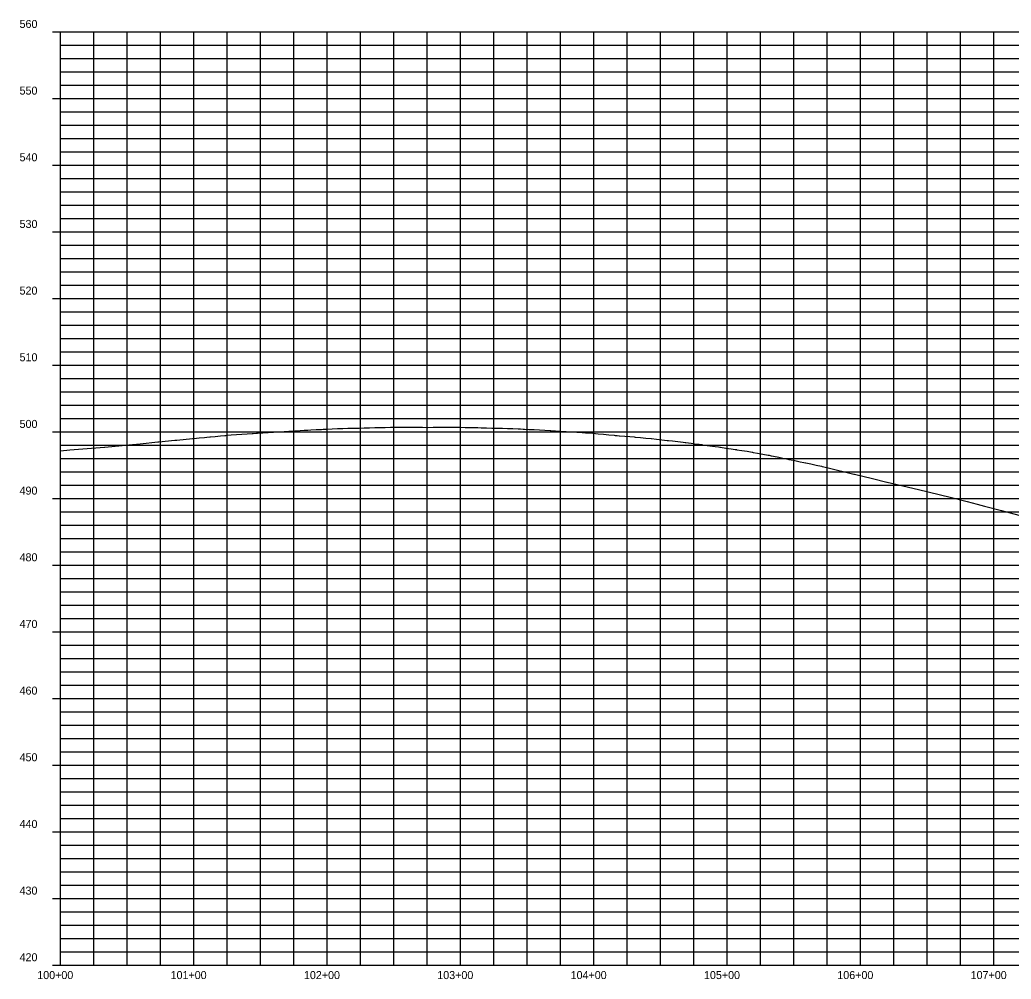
# Model space of a CAD drawing. Extents: x 1054002 to 1056762, y 395173 to 397393.
# Drawn here: x 1054002 to 1054745, y 396673 to 397393 of the extents above; entities that cross this region are included whole.
import ezdxf

# ---------------------------------------------------------------- set-up
doc = ezdxf.new("R2010")
doc.units = 0
for name, color, linetype in [('63', 7, 'Continuous'), ('R_Axis_Annotation', 7, 'Continuous'), ('R_Exist Surface', 7, 'Continuous'), ('R_Grid', 7, 'Continuous'), ('R_Grid Annot', 7, 'Continuous'), ('R_Grid_Minor', 7, 'Continuous')]:
    doc.layers.add(name, color=color, linetype=linetype)

msp = doc.modelspace()

# ---------------------------------------------------------------- linework, layer by layer
at = {"layer": 'R_Exist Surface'}
msp.add_lwpolyline([(1054032.29, 397069.3), (1054039.34, 397069.89), (1054039.43, 397069.9), (1054052.41, 397070.98), (1054052.42, 397070.98), (1054065.39, 397072.06), (1054065.47, 397072.06), (1054078.44, 397073.14), (1054083.55, 397073.66), (1054092.06, 397074.53), (1054105.29, 397075.88), (1054105.96, 397075.96), (1054118.16, 397077.16), (1054119.57, 397077.31), (1054131.32, 397078.47), (1054132.29, 397078.57), (1054136.28, 397078.96), (1054140.27, 397079.34), (1054142.1, 397079.51), (1054144.26, 397079.74), (1054144.8, 397079.8), (1054148.25, 397080.11), (1054152.24, 397080.47), (1054155.52, 397080.76), (1054156.23, 397080.83), (1054157.51, 397080.95), (1054160.22, 397081.15), (1054164.21, 397081.45), (1054168.19, 397081.73), (1054172.18, 397082.01), (1054176.17, 397082.27), (1054176.75, 397082.31), (1054179.26, 397082.51), (1054180.16, 397082.58), (1054181.65, 397082.7), (1054184.15, 397082.85), (1054188.14, 397083.09), (1054192.13, 397083.31), (1054196.12, 397083.53), (1054200.11, 397083.73), (1054202.29, 397083.83), (1054203.65, 397083.92), (1054204.1, 397083.95), (1054208.09, 397084.21), (1054212.08, 397084.45), (1054214.94, 397084.62), (1054216.06, 397084.7), (1054217.75, 397084.82), (1054220.05, 397084.95), (1054224.04, 397085.16), (1054228.03, 397085.35), (1054229.28, 397085.41), (1054231.43, 397085.54), (1054232.02, 397085.56), (1054236.01, 397085.72), (1054240, 397085.87), (1054242.91, 397085.97), (1054243.99, 397086.01), (1054247.91, 397086.12), (1054247.98, 397086.12), (1054251.97, 397086.22), (1054255.49, 397086.29), (1054255.96, 397086.31), (1054256.25, 397086.32), (1054259.95, 397086.44), (1054263.93, 397086.56), (1054267.92, 397086.66), (1054268.32, 397086.67), (1054268.68, 397086.68), (1054271.91, 397086.75), (1054275.9, 397086.82), (1054279.89, 397086.87), (1054281.12, 397086.88), (1054281.54, 397086.89), (1054283.88, 397086.91), (1054287.87, 397086.93), (1054291.86, 397086.94), (1054293.91, 397086.94), (1054294.92, 397086.94), (1054295.85, 397086.94), (1054299.84, 397086.92), (1054303.83, 397086.88), (1054306.73, 397086.84), (1054307.81, 397086.86), (1054311.8, 397086.9), (1054315.79, 397086.92), (1054318.11, 397086.92), (1054319.78, 397086.94), (1054320.3, 397086.94), (1054323.77, 397086.93), (1054327.76, 397086.91), (1054331.75, 397086.87), (1054331.82, 397086.87), (1054335.74, 397086.81), (1054339.73, 397086.75), (1054343.52, 397086.67), (1054343.72, 397086.66), (1054345.39, 397086.64), (1054347.71, 397086.58), (1054351.7, 397086.47), (1054355.68, 397086.35), (1054356.97, 397086.3), (1054359.67, 397086.24), (1054363.66, 397086.14), (1054367.65, 397086.02), (1054371.64, 397085.89), (1054375.63, 397085.75), (1054377.2, 397085.69), (1054379.22, 397085.55), (1054379.62, 397085.54), (1054380.23, 397085.51), (1054383.61, 397085.36), (1054387.6, 397085.17), (1054391.59, 397084.97), (1054395.58, 397084.74), (1054399.57, 397084.5), (1054400.14, 397084.47), (1054401.93, 397084.35), (1054403.55, 397084.27), (1054407.54, 397084.05), (1054411.53, 397083.81), (1054415.52, 397083.56), (1054419.51, 397083.29), (1054423.5, 397083.01), (1054424.44, 397082.94), (1054425.24, 397082.87), (1054426.11, 397082.79), (1054427.49, 397082.68), (1054431.48, 397082.37), (1054435.47, 397082.03), (1054439.46, 397081.68), (1054443.45, 397081.31), (1054447.44, 397080.92), (1054448.33, 397080.83), (1054449.82, 397080.71), (1054451.18, 397080.6), (1054451.42, 397080.58), (1054455.41, 397080.26), (1054459.4, 397079.92), (1054462.6, 397079.63), (1054463.17, 397079.58), (1054463.39, 397079.56), (1054467.38, 397079.19), (1054471.37, 397078.8), (1054475.35, 397078.39), (1054475.36, 397078.39), (1054475.49, 397078.38), (1054479.35, 397077.97), (1054483.34, 397077.53), (1054487.33, 397077.08), (1054488.05, 397076.99), (1054488.21, 397076.98), (1054491.32, 397076.62), (1054495.3, 397076.13), (1054499.29, 397075.63), (1054500.72, 397075.45), (1054501.29, 397075.39), (1054503.28, 397075.15), (1054507.27, 397074.66), (1054507.61, 397074.61), (1054511.26, 397074.15), (1054513.27, 397073.88), (1054513.72, 397073.82), (1054515.25, 397073.61), (1054519.24, 397073.07), (1054523.23, 397072.51), (1054525.78, 397072.15), (1054526.86, 397071.98), (1054527.22, 397071.93), (1054531.21, 397071.35), (1054535.2, 397070.76), (1054538.34, 397070.28), (1054539.19, 397070.14), (1054539.57, 397070.08), (1054543.17, 397069.52), (1054547.16, 397068.89), (1054550.98, 397068.27), (1054551.15, 397068.24), (1054551.89, 397068.11), (1054555.14, 397067.51), (1054559.13, 397066.76), (1054563.12, 397066), (1054563.76, 397065.87), (1054565.38, 397065.52), (1054567.11, 397065.18), (1054571.1, 397064.39), (1054575.09, 397063.59), (1054576.69, 397063.27), (1054578.51, 397062.85), (1054579.08, 397062.74), (1054583.07, 397061.92), (1054587.06, 397061.1), (1054589.75, 397060.54), (1054591.04, 397060.23), (1054591.24, 397060.19), (1054595.03, 397059.39), (1054599.02, 397058.55), (1054602.93, 397057.73), (1054603.01, 397057.71), (1054603.56, 397057.57), (1054607, 397056.74), (1054627.31, 397051.81), (1054627.67, 397051.71), (1054641.33, 397048.4), (1054651.9, 397045.84), (1054652.22, 397045.76), (1054675.65, 397040.19), (1054675.84, 397040.14), (1054699.4, 397034.54), (1054699.43, 397034.54), (1054712.29, 397031.18), (1054712.3, 397031.18), (1054719.75, 397029.24), (1054725.17, 397027.82), (1054738.01, 397024.47), (1054738.07, 397024.45), (1054750.91, 397021.1)], dxfattribs=at)
at = {"layer": 'R_Grid'}
for p, q in [((1054032.29, 396683.41), (1054032.29, 397383.41)), ((1054032.29, 397383.41), (1056732.29, 397383.41)), ((1054032.29, 397383.41), (1056732.29, 397383.41)), ((1054132.29, 396683.41), (1054132.29, 397383.41)), ((1054232.29, 396683.41), (1054232.29, 397383.41)), ((1054332.29, 396683.41), (1054332.29, 397383.41)), ((1054432.29, 396683.41), (1054432.29, 397383.41)), ((1054532.29, 396683.41), (1054532.29, 397383.41)), ((1054632.29, 396683.41), (1054632.29, 397383.41)), ((1054732.29, 396683.41), (1054732.29, 397383.41)), ((1054032.29, 397333.41), (1056732.29, 397333.41)), ((1054032.29, 397283.41), (1056732.29, 397283.41)), ((1054032.29, 397233.41), (1056732.29, 397233.41)), ((1054032.29, 397183.41), (1056732.29, 397183.41)), ((1054032.29, 397133.41), (1056732.29, 397133.41)), ((1054032.29, 397083.41), (1056732.29, 397083.41)), ((1054032.29, 397033.41), (1056732.29, 397033.41)), ((1054032.29, 396983.41), (1056732.29, 396983.41)), ((1054032.29, 396933.41), (1056732.29, 396933.41)), ((1054032.29, 396883.41), (1056732.29, 396883.41)), ((1054032.29, 396833.41), (1056732.29, 396833.41)), ((1054032.29, 396783.41), (1056732.29, 396783.41)), ((1054032.29, 396733.41), (1056732.29, 396733.41)), ((1054032.29, 396683.41), (1056732.29, 396683.41))]:
    msp.add_line(p, q, dxfattribs=at)
at = {"layer": 'R_Grid Annot'}
for p, q in [((1054026.29, 397383.41), (1054032.29, 397383.41)), ((1054026.29, 397383.41), (1054032.29, 397383.41)), ((1054032.29, 397373.41), (1054035.29, 397373.41)), ((1054032.29, 397363.41), (1054035.29, 397363.41)), ((1054032.29, 397353.41), (1054035.29, 397353.41)), ((1054032.29, 397343.41), (1054035.29, 397343.41)), ((1054026.29, 397333.41), (1054032.29, 397333.41)), ((1054032.29, 397323.41), (1054035.29, 397323.41)), ((1054032.29, 397313.41), (1054035.29, 397313.41)), ((1054032.29, 397303.41), (1054035.29, 397303.41)), ((1054032.29, 397293.41), (1054035.29, 397293.41)), ((1054026.29, 397283.41), (1054032.29, 397283.41)), ((1054032.29, 397273.41), (1054035.29, 397273.41)), ((1054032.29, 397263.41), (1054035.29, 397263.41)), ((1054032.29, 397253.41), (1054035.29, 397253.41)), ((1054032.29, 397243.41), (1054035.29, 397243.41)), ((1054026.29, 397233.41), (1054032.29, 397233.41)), ((1054032.29, 397223.41), (1054035.29, 397223.41)), ((1054032.29, 397213.41), (1054035.29, 397213.41)), ((1054032.29, 397203.41), (1054035.29, 397203.41)), ((1054032.29, 397193.41), (1054035.29, 397193.41)), ((1054026.29, 397183.41), (1054032.29, 397183.41)), ((1054032.29, 397173.41), (1054035.29, 397173.41)), ((1054032.29, 397163.41), (1054035.29, 397163.41)), ((1054032.29, 397153.41), (1054035.29, 397153.41)), ((1054032.29, 397143.41), (1054035.29, 397143.41)), ((1054026.29, 397133.41), (1054032.29, 397133.41)), ((1054032.29, 397123.41), (1054035.29, 397123.41)), ((1054032.29, 397113.41), (1054035.29, 397113.41)), ((1054032.29, 397103.41), (1054035.29, 397103.41)), ((1054032.29, 397093.41), (1054035.29, 397093.41)), ((1054026.29, 397083.41), (1054032.29, 397083.41)), ((1054032.29, 397073.41), (1054035.29, 397073.41)), ((1054032.29, 397063.41), (1054035.29, 397063.41)), ((1054032.29, 397053.41), (1054035.29, 397053.41)), ((1054032.29, 397043.41), (1054035.29, 397043.41)), ((1054026.29, 397033.41), (1054032.29, 397033.41)), ((1054032.29, 397023.41), (1054035.29, 397023.41)), ((1054032.29, 397013.41), (1054035.29, 397013.41)), ((1054032.29, 397003.41), (1054035.29, 397003.41)), ((1054032.29, 396993.41), (1054035.29, 396993.41)), ((1054026.29, 396983.41), (1054032.29, 396983.41)), ((1054032.29, 396973.41), (1054035.29, 396973.41)), ((1054032.29, 396963.41), (1054035.29, 396963.41)), ((1054032.29, 396953.41), (1054035.29, 396953.41)), ((1054032.29, 396943.41), (1054035.29, 396943.41)), ((1054026.29, 396933.41), (1054032.29, 396933.41)), ((1054032.29, 396923.41), (1054035.29, 396923.41)), ((1054032.29, 396913.41), (1054035.29, 396913.41)), ((1054032.29, 396903.41), (1054035.29, 396903.41)), ((1054032.29, 396893.41), (1054035.29, 396893.41)), ((1054026.29, 396883.41), (1054032.29, 396883.41)), ((1054032.29, 396873.41), (1054035.29, 396873.41)), ((1054032.29, 396863.41), (1054035.29, 396863.41)), ((1054032.29, 396853.41), (1054035.29, 396853.41)), ((1054032.29, 396843.41), (1054035.29, 396843.41)), ((1054026.29, 396833.41), (1054032.29, 396833.41)), ((1054032.29, 396823.41), (1054035.29, 396823.41)), ((1054032.29, 396813.41), (1054035.29, 396813.41)), ((1054032.29, 396803.41), (1054035.29, 396803.41)), ((1054032.29, 396793.41), (1054035.29, 396793.41)), ((1054026.29, 396783.41), (1054032.29, 396783.41)), ((1054032.29, 396773.41), (1054035.29, 396773.41)), ((1054032.29, 396763.41), (1054035.29, 396763.41)), ((1054032.29, 396753.41), (1054035.29, 396753.41)), ((1054032.29, 396743.41), (1054035.29, 396743.41)), ((1054026.29, 396733.41), (1054032.29, 396733.41)), ((1054032.29, 396723.41), (1054035.29, 396723.41)), ((1054032.29, 396713.41), (1054035.29, 396713.41)), ((1054032.29, 396703.41), (1054035.29, 396703.41)), ((1054032.29, 396693.41), (1054035.29, 396693.41)), ((1054026.29, 396683.41), (1054032.29, 396683.41))]:
    msp.add_line(p, q, dxfattribs=at)
at = {"layer": 'R_Grid_Minor'}
for p, q in [((1054057.29, 396683.41), (1054057.29, 397383.41)), ((1054082.29, 396683.41), (1054082.29, 397383.41)), ((1054107.29, 396683.41), (1054107.29, 397383.41)), ((1054157.29, 396683.41), (1054157.29, 397383.41)), ((1054182.29, 396683.41), (1054182.29, 397383.41)), ((1054207.29, 396683.41), (1054207.29, 397383.41)), ((1054257.29, 396683.41), (1054257.29, 397383.41)), ((1054282.29, 396683.41), (1054282.29, 397383.41)), ((1054307.29, 396683.41), (1054307.29, 397383.41)), ((1054357.29, 396683.41), (1054357.29, 397383.41)), ((1054382.29, 396683.41), (1054382.29, 397383.41)), ((1054407.29, 396683.41), (1054407.29, 397383.41)), ((1054457.29, 396683.41), (1054457.29, 397383.41)), ((1054482.29, 396683.41), (1054482.29, 397383.41)), ((1054507.29, 396683.41), (1054507.29, 397383.41)), ((1054557.29, 396683.41), (1054557.29, 397383.41)), ((1054582.29, 396683.41), (1054582.29, 397383.41)), ((1054607.29, 396683.41), (1054607.29, 397383.41)), ((1054657.29, 396683.41), (1054657.29, 397383.41)), ((1054682.29, 396683.41), (1054682.29, 397383.41)), ((1054707.29, 396683.41), (1054707.29, 397383.41)), ((1054032.29, 397373.41), (1056732.29, 397373.41)), ((1054032.29, 397363.41), (1056732.29, 397363.41)), ((1054032.29, 397353.41), (1056732.29, 397353.41)), ((1054032.29, 397343.41), (1056732.29, 397343.41)), ((1054032.29, 397323.41), (1056732.29, 397323.41)), ((1054032.29, 397313.41), (1056732.29, 397313.41)), ((1054032.29, 397303.41), (1056732.29, 397303.41)), ((1054032.29, 397293.41), (1056732.29, 397293.41)), ((1054032.29, 397273.41), (1056732.29, 397273.41)), ((1054032.29, 397263.41), (1056732.29, 397263.41)), ((1054032.29, 397253.41), (1056732.29, 397253.41)), ((1054032.29, 397243.41), (1056732.29, 397243.41)), ((1054032.29, 397223.41), (1056732.29, 397223.41)), ((1054032.29, 397213.41), (1056732.29, 397213.41)), ((1054032.29, 397203.41), (1056732.29, 397203.41)), ((1054032.29, 397193.41), (1056732.29, 397193.41)), ((1054032.29, 397173.41), (1056732.29, 397173.41)), ((1054032.29, 397163.41), (1056732.29, 397163.41)), ((1054032.29, 397153.41), (1056732.29, 397153.41)), ((1054032.29, 397143.41), (1056732.29, 397143.41)), ((1054032.29, 397123.41), (1056732.29, 397123.41)), ((1054032.29, 397113.41), (1056732.29, 397113.41)), ((1054032.29, 397103.41), (1056732.29, 397103.41)), ((1054032.29, 397093.41), (1056732.29, 397093.41)), ((1054032.29, 397073.41), (1056732.29, 397073.41)), ((1054032.29, 397063.41), (1056732.29, 397063.41)), ((1054032.29, 397053.41), (1056732.29, 397053.41)), ((1054032.29, 397043.41), (1056732.29, 397043.41)), ((1054032.29, 397023.41), (1056732.29, 397023.41)), ((1054032.29, 397013.41), (1056732.29, 397013.41)), ((1054032.29, 397003.41), (1056732.29, 397003.41)), ((1054032.29, 396993.41), (1056732.29, 396993.41)), ((1054032.29, 396973.41), (1056732.29, 396973.41)), ((1054032.29, 396963.41), (1056732.29, 396963.41)), ((1054032.29, 396953.41), (1056732.29, 396953.41)), ((1054032.29, 396943.41), (1056732.29, 396943.41)), ((1054032.29, 396923.41), (1056732.29, 396923.41)), ((1054032.29, 396913.41), (1056732.29, 396913.41)), ((1054032.29, 396903.41), (1056732.29, 396903.41)), ((1054032.29, 396893.41), (1056732.29, 396893.41)), ((1054032.29, 396873.41), (1056732.29, 396873.41)), ((1054032.29, 396863.41), (1056732.29, 396863.41)), ((1054032.29, 396853.41), (1056732.29, 396853.41)), ((1054032.29, 396843.41), (1056732.29, 396843.41)), ((1054032.29, 396823.41), (1056732.29, 396823.41)), ((1054032.29, 396813.41), (1056732.29, 396813.41)), ((1054032.29, 396803.41), (1056732.29, 396803.41)), ((1054032.29, 396793.41), (1056732.29, 396793.41)), ((1054032.29, 396773.41), (1056732.29, 396773.41)), ((1054032.29, 396763.41), (1056732.29, 396763.41)), ((1054032.29, 396753.41), (1056732.29, 396753.41)), ((1054032.29, 396743.41), (1056732.29, 396743.41)), ((1054032.29, 396723.41), (1056732.29, 396723.41)), ((1054032.29, 396713.41), (1056732.29, 396713.41)), ((1054032.29, 396703.41), (1056732.29, 396703.41)), ((1054032.29, 396693.41), (1056732.29, 396693.41))]:
    msp.add_line(p, q, dxfattribs=at)

# ---------------------------------------------------------------- texts
at = {"layer": '63'}
msp.add_text('-', height=0.0001, dxfattribs=at).set_placement((1054032.29, 396683.41))
at = {"layer": 'R_Axis_Annotation'}
for s, p in [('560', (1054001.62, 397386.41)), ('560', (1054001.62, 397386.41)), ('550', (1054001.62, 397336.41)), ('540', (1054001.62, 397286.41)), ('530', (1054001.62, 397236.41)), ('520', (1054001.62, 397186.41)), ('510', (1054001.62, 397136.41)), ('500', (1054001.62, 397086.41)), ('490', (1054001.62, 397036.41)), ('480', (1054001.62, 396986.41)), ('470', (1054001.62, 396936.41)), ('460', (1054001.62, 396886.41)), ('450', (1054001.62, 396836.41)), ('440', (1054001.62, 396786.41)), ('430', (1054001.62, 396736.41)), ('420', (1054001.62, 396686.41)), ('100+00', (1054014.89, 396673.06)), ('101+00', (1054114.89, 396673.06)), ('102+00', (1054214.89, 396673.06)), ('103+00', (1054314.89, 396673.06)), ('104+00', (1054414.89, 396673.06)), ('105+00', (1054514.89, 396673.06)), ('106+00', (1054614.89, 396673.06)), ('107+00', (1054714.89, 396673.06))]:
    msp.add_text(s, height=6, dxfattribs=at).set_placement(p)

doc.saveas('drawing.dxf')
